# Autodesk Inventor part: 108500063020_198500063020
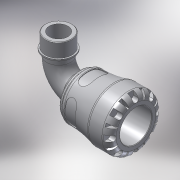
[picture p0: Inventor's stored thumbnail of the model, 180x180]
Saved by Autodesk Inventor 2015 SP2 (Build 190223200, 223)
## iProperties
Created: 2016-12
Part Number: 108500063020_198500063020
Material: PVC-Piping
Description: PLASSON 90° ELBOW WITH THREADED MALE OFFTAKE 63X2" SERIES 1
Document SubType Name: Modeling
Designer: KIM
Mass: 733.266 g
Surface Area: 958.932 cm^2
Volume: 523.761 cm^3
Density: 1.4 g/cm^3
Appearance: Smooth - White
Author: KIM
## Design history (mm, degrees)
derived "1085.ipt"
feature "Solid1::1085.ipt"
tag "TaggingFeature1"
body "Solid1"
other parameters: "d1" = 37.8, "d2" = 63, "d3" = 78.75, "d4" = 103, "d8" = 87.55, "d13" = 9.7, "d14" = 9.7, "d15" = 0, "d17" = 360 deg, "d19" = 8 deg, "d20" = 1.26, "d21" = 1.26, "d22" = 8 deg, "d24" = 0, "d26" = 360 deg, "d33" = 10.3, "d43" = 80.34, "d51" = 1.03, "d54" = 22.05, "d55" = 13.86, "d57" = 19.012, "d58" = 0, "d74" = 0, "d82" = 1.26, "d115" = 360 deg, "d207" = 90 deg, "d228" = 18.7425, "d247" = 2.06, "d248" = 5.4, "d268" = 48.1525, "d269" = 5.4, "d270" = 143, "d276" = 59.614, "d277" = 25, "d278" = 65.5754, "d279" = 81, "d280" = 27.5, "d281" = 8.9421, "d283" = 53.6526, "d286" = 0, "d287" = 0, "d288" = 41.7298, "d290" = 13.3437, "d292" = 30 deg, "d_" = 63, "E_" = 103, "A_" = 143, "A_1" = 81, "l_2" = 25, "R_" = 59.614, "d9" = 12.125, "d11" = 103, "d12" = 78.75, "d289" = 41.7298
